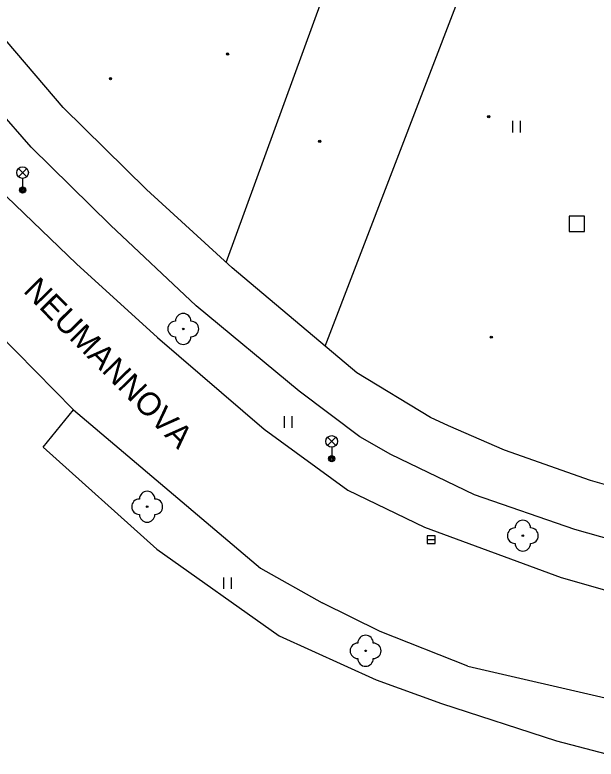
# Model space of a CAD drawing. Extents: x -641829 to -641525, y -1114855 to -1114359.
# Drawn here: x -641663.25 to -641625.7, y -1114533.67 to -1114485.57 of the extents above; entities that cross this region are included whole.
import ezdxf

# ---------------------------------------------------------------- set-up
doc = ezdxf.new("R2010")
doc.units = 0
for name, color, linetype in [('Vrstva 10', 7, 'Continuous'), ('Vrstva 11', 7, 'Continuous'), ('Vrstva 14', 7, 'Continuous'), ('Vrstva 20', 7, 'Continuous'), ('Vrstva 22', 7, 'Continuous'), ('Vrstva 26', 7, 'Continuous'), ('Vrstva 27', 7, 'Continuous'), ('Vrstva 33', 7, 'Continuous'), ('Vrstva 36', 7, 'Continuous'), ('Vrstva 49', 7, 'Continuous')]:
    doc.layers.add(name, color=color, linetype=linetype)

msp = doc.modelspace()

# ---------------------------------------------------------------- linework, layer by layer
at = {"layer": 'Vrstva 10'}
for p, q in [((-641663.78, -1114497.32), (-641659.26, -1114501.67)), ((-641671.62, -1114498.73), (-641659.47, -1114511.09)), ((-641659.26, -1114501.67), (-641654.03, -1114506.42)), ((-641654.03, -1114506.42), (-641647.15, -1114512.35)), ((-641661.41, -1114513.5), (-641659.47, -1114511.09)), ((-641659.47, -1114511.09), (-641647.38, -1114521.32)), ((-641647.15, -1114512.35), (-641641.74, -1114516.28)), ((-641661.41, -1114513.5), (-641654.07, -1114520.11)), ((-641641.74, -1114516.28), (-641636.79, -1114518.69)), ((-641636.79, -1114518.69), (-641627.95, -1114521.94)), ((-641654.07, -1114520.11), (-641646.17, -1114525.7)), ((-641647.38, -1114521.32), (-641643.4, -1114523.58)), ((-641627.95, -1114521.94), (-641621.63, -1114523.72)), ((-641639.64, -1114525.42), (-641643.4, -1114523.58)), ((-641646.17, -1114525.7), (-641639.91, -1114528.54)), ((-641633.98, -1114527.66), (-641639.64, -1114525.42)), ((-641633.98, -1114527.66), (-641623.24, -1114530.15)), ((-641639.91, -1114528.54), (-641635.68, -1114530.07)), ((-641635.68, -1114530.07), (-641628.25, -1114532.49)), ((-641628.25, -1114532.49), (-641623.76, -1114533.67))]:
    msp.add_line(p, q, dxfattribs=at)
at = {"layer": 'Vrstva 11'}
for p, q in [((-641660.12, -1114491.55), (-641664.6, -1114486.32)), ((-641662.19, -1114494.13), (-641667.48, -1114488.09)), ((-641654.74, -1114496.85), (-641660.12, -1114491.55)), ((-641657.06, -1114499.17), (-641662.19, -1114494.13)), ((-641649.2, -1114501.93), (-641654.74, -1114496.85)), ((-641651.53, -1114504.38), (-641657.06, -1114499.17)), ((-641641.16, -1114508.7), (-641649.2, -1114501.93)), ((-641644.89, -1114509.89), (-641651.53, -1114504.38)), ((-641636.4, -1114511.59), (-641641.16, -1114508.7)), ((-641640.97, -1114512.85), (-641644.89, -1114509.89)), ((-641635.24, -1114512.13), (-641636.4, -1114511.59)), ((-641631.62, -1114513.7), (-641635.24, -1114512.13)), ((-641638.95, -1114513.98), (-641640.97, -1114512.85)), ((-641626.06, -1114515.66), (-641631.62, -1114513.7)), ((-641633.56, -1114516.58), (-641638.95, -1114513.98)), ((-641620.51, -1114517.23), (-641626.06, -1114515.66)), ((-641627.08, -1114518.84), (-641633.56, -1114516.58)), ((-641621.55, -1114520.39), (-641627.08, -1114518.84))]:
    msp.add_line(p, q, dxfattribs=at)
at = {"layer": 'Vrstva 14'}
for p, q in [((-641649.59, -1114501.58), (-641641.7, -1114479.87)), ((-641643.19, -1114506.99), (-641633.35, -1114481.33))]:
    msp.add_line(p, q, dxfattribs=at)
at = {"layer": 'Vrstva 20'}
for centre, radius in [((-641649.51, -1114488.09), 0.075), ((-641649.51, -1114488.09), 0.0204), ((-641657.07, -1114489.69), 0.075), ((-641657.07, -1114489.69), 0.0204), ((-641632.63, -1114492.15), 0.075), ((-641632.63, -1114492.15), 0.0204), ((-641643.55, -1114493.75), 0.075), ((-641643.55, -1114493.75), 0.0204), ((-641632.47, -1114506.4), 0.075), ((-641632.47, -1114506.4), 0.0204)]:
    msp.add_circle(centre, radius, dxfattribs=at)
at = {"layer": 'Vrstva 22'}
for centre in [(-641652.37, -1114505.87), (-641654.7, -1114517.36), (-641630.43, -1114519.23), (-641640.59, -1114526.67)]:
    msp.add_circle(centre, 0.05, dxfattribs=at)
for centre, start, end in [((-641652.37, -1114505.37), 0, 180), ((-641652.87, -1114505.87), 90, 270), ((-641651.87, -1114505.87), 270, 90), ((-641652.37, -1114506.37), 180, 0), ((-641654.7, -1114516.86), 0, 180), ((-641655.2, -1114517.36), 90, 270), ((-641654.2, -1114517.36), 270, 90), ((-641654.7, -1114517.86), 180, 0), ((-641630.43, -1114518.73), 0, 180), ((-641630.93, -1114519.23), 90, 270), ((-641629.93, -1114519.23), 270, 90), ((-641630.43, -1114519.73), 180, 0), ((-641640.59, -1114526.17), 0, 180), ((-641641.09, -1114526.67), 90, 270), ((-641640.09, -1114526.67), 270, 90), ((-641640.59, -1114527.17), 180, 0)]:
    msp.add_arc(centre, 0.5, start, end, dxfattribs=at)
at = {"layer": 'Vrstva 26'}
msp.add_lwpolyline([(-641627.44, -1114499.58), (-641626.44, -1114499.58), (-641626.44, -1114498.58), (-641627.44, -1114498.58)], close=True, dxfattribs=at)
at = {"layer": 'Vrstva 27'}
msp.add_line((-641636.1, -1114519.49), (-641636.6, -1114519.49), dxfattribs=at)
msp.add_lwpolyline([(-641636.1, -1114519.24), (-641636.6, -1114519.24), (-641636.6, -1114519.74), (-641636.1, -1114519.74)], close=True, dxfattribs=at)
at = {"layer": 'Vrstva 33'}
for p, q in [((-641663.014, -1114496.03), (-641662.486, -1114495.5)), ((-641663.014, -1114495.5), (-641662.486, -1114496.03)), ((-641662.75, -1114496.14), (-641662.75, -1114496.89)), ((-641643.044, -1114513.4), (-641642.516, -1114512.87)), ((-641643.044, -1114512.87), (-641642.516, -1114513.4)), ((-641642.78, -1114513.51), (-641642.78, -1114514.26))]:
    msp.add_line(p, q, dxfattribs=at)
for centre, radius in [((-641662.75, -1114495.765), 0.375), ((-641662.75, -1114496.89), 0.2), ((-641662.75, -1114496.89), 0.145), ((-641662.75, -1114496.89), 0.0876), ((-641642.78, -1114513.135), 0.375), ((-641642.78, -1114514.26), 0.2), ((-641642.78, -1114514.26), 0.145), ((-641642.78, -1114514.26), 0.0876)]:
    msp.add_circle(centre, radius, dxfattribs=at)
at = {"layer": 'Vrstva 36'}
for p, q in [((-641631.084, -1114493.174), (-641631.084, -1114492.422)), ((-641630.584, -1114493.174), (-641630.584, -1114492.422)), ((-641645.834, -1114512.254), (-641645.834, -1114511.502)), ((-641645.334, -1114512.254), (-641645.334, -1114511.502)), ((-641649.744, -1114522.672), (-641649.744, -1114521.924)), ((-641649.244, -1114522.672), (-641649.244, -1114521.924))]:
    msp.add_line(p, q, dxfattribs=at)

# ---------------------------------------------------------------- texts
at = {"layer": 'Vrstva 49'}
msp.add_text('NEUMANNOVA', height=1.5, rotation=314.4996, dxfattribs=at).set_placement((-641662.77, -1114503.45))

doc.saveas('drawing.dxf')
